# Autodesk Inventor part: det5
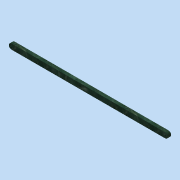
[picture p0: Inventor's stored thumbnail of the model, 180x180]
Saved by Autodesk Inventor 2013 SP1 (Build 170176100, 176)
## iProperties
Created: 2016-04
Part Number: det5
Material: Пластик АБС
Document SubType Name: Modeling
Designer: Кравец
Density: 1 g/cm^3
Author: Кравец
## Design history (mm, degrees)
sketch "Эскиз1"
  geometry: L1 (43.9, -1.5)-(-43.9, -1.5); L2 (-43.9, -1.5)-(-43.9, 1.5); L3 (-43.9, 1.5)-(43.9, 1.5); L4 (43.9, 1.5)-(43.9, -1.5); L5 (43.9, -1.5)-(-43.9, 1.5); L6 (-43.9, -1.5)-(43.9, 1.5); A1 r 1.5 centre (-43.9, 0) between (-43.9, 1.5) and (-43.9, -1.5); A2 r 1.5 centre (43.9, 0) between (43.9, -1.5) and (43.9, 1.5); 1 further point
  constraints: 12 end point, 4 point on circle, 4 tangent, 2 centre point, 2 midpoint, 2 parallel, 1 horizontal, 1 perpendicular
  dimensions: "d0" = 3 distance between parallel lines of L1 L3; "d2" = 87.8 distance of L2.end L3.end
extrude "Выдавливание1" new body sketch "Эскиз1" distance "d3" = 1.9; taper "d4" = 0 deg
sketch "Эскиз2"
  geometry: C1 r 0.5 at (43.9, 0); C2 r 0.5 at (-43.9, 0); A1 r 1.5 centre (-43.9, 0) between (-43.9, 1.5) and (-43.9, -1.5) reference; A2 r 1.5 centre (43.9, 0) between (43.9, -1.5) and (43.9, 1.5) reference; 1 further point
  constraints: 2 centre point, 2 coincident, 1 equal radius
  dimensions: "d5" = 1 diameter of C2
extrude "Выдавливание2" join sketch "Эскиз2" distance "d7" = 0.5; taper "d8" = 0 deg
fillet "Сопряжение1" dims "d9" = 0.5
sketch "Эскиз3"
  geometry: C1 r 0.5 at (-43.9, 0); C2 r 0.5 at (43.9, 0); A1 r 1.5 centre (-43.9, 0) between (-43.9, 1.5) and (-43.9, -1.5) reference; A2 r 1.5 centre (43.9, 0) between (43.9, -1.5) and (43.9, 1.5) reference; 1 further point
  constraints: 2 centre point, 2 coincident, 1 equal radius
  dimensions: "d10" = 1 diameter of C1
extrude "Выдавливание3" join sketch "Эскиз3" distance "d12" = 0.5; taper "d13" = 0 deg
fillet "Сопряжение2" dims "d14" = 0.5
node "Твердое тело1"
